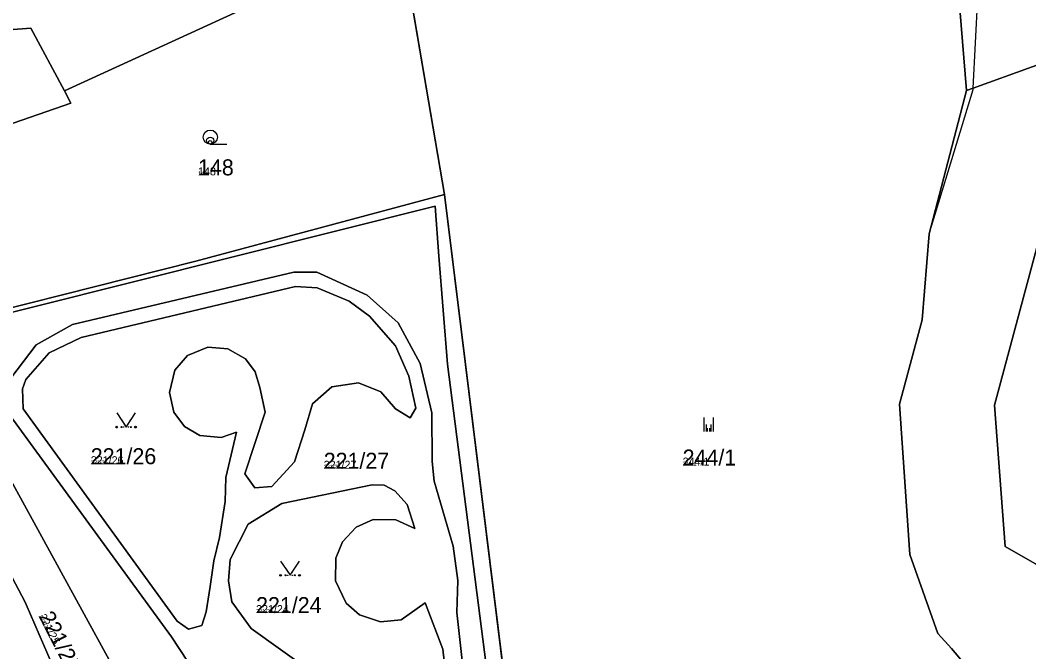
# Model space of a CAD drawing. Extents: x -759873 to -758487, y -975024 to -973516.
# Drawn here: x -759272.8 to -759165.8, y -974542 to -974475 of the extents above; entities that cross this region are included whole.
import ezdxf

# ---------------------------------------------------------------- set-up
doc = ezdxf.new("R2010")
doc.units = 0
for name, color, linetype in [('KAT_02_hranice parcel', 7, 'Continuous'), ('KAT_03_1000_čísla parcelní', 7, 'Continuous'), ('KAT_03_250_čísla parcelní', 7, 'Continuous'), ('KAT_03_500_čísla parcelní', 7, 'Continuous'), ('KAT_04_vnitřní kresba', 7, 'Continuous'), ('KAT_05_1000_značky kultur', 7, 'Continuous'), ('KAT_05_250_značky kultur', 7, 'Continuous'), ('KAT_05_500_značky kultur', 7, 'Continuous'), ('KAT_14_plocha_pozemek', 7, 'Continuous')]:
    doc.layers.add(name, color=color, linetype=linetype)

msp = doc.modelspace()

# ---------------------------------------------------------------- linework, layer by layer
at = {"layer": 'KAT_02_hranice parcel'}
for p, q in [((-759227.79, -974493.47), (-759232.25, -974467.32)), ((-759268.15, -974482.46), (-759249.19, -974473.79)), ((-759219.91, -974557.23), (-759227.79, -974493.47))]:
    msp.add_line(p, q, dxfattribs=at)
for points in [[(-759191.99, -974436.47), (-759175.27, -974446.88), (-759172.37, -974482.45)], [(-759293.31, -974472.92), (-759292.86, -974472.72), (-759290.03, -974471.45), (-759286.14, -974469.75), (-759281.32, -974467.51), (-759277.88, -974471.27), (-759274.04, -974476.01), (-759271.7, -974475.81), (-759268.15, -974482.46)], [(-759172.37, -974482.45), (-759171.66, -974482.19), (-759159.14, -974477.67)], [(-759275.54, -974505.92), (-759276.79, -974504.06), (-759278.82, -974487.7), (-759267.45, -974483.78), (-759268.15, -974482.46)], [(-759124.04, -974618.94), (-759128.67, -974614.12), (-759132.72, -974605.42), (-759137.89, -974601.46), (-759140.41, -974591.83), (-759141.66, -974587.58), (-759147.81, -974582.84), (-759161.09, -974585.41), (-759165.12, -974579.47), (-759166.21, -974570.14), (-759161.85, -974571.03), (-759164.75, -974552.56), (-759173.97, -974541.64), (-759175.43, -974540.05), (-759178.37, -974531.68), (-759179.47, -974515.71), (-759177.07, -974506.79), (-759176.34, -974497.63), (-759172.37, -974482.45)], [(-759149.95, -974565.4), (-759151.3, -974564.28), (-759155.66, -974538.03), (-759168.27, -974530.82), (-759169.41, -974515.83), (-759161.57, -974486.7)], [(-759275.54, -974505.92), (-759254.2, -974500.54), (-759227.79, -974493.47)], [(-759219.91, -974557.23), (-759223.23, -974544.52), (-759227.46, -974511.48), (-759228.38, -974500), (-759228.8, -974494.72), (-759282.45, -974508.14), (-759262.36, -974544.72), (-759253.18, -974586.18)], [(-759273.84, -974512.95), (-759271.16, -974509.41), (-759267.29, -974507.26), (-759243.79, -974501.7), (-759241.36, -974501.72), (-759236.02, -974504.15), (-759232.73, -974507.08), (-759230.36, -974511.4), (-759229.15, -974516.63), (-759229.1, -974521.82), (-759228.9, -974523.89), (-759226.87, -974530.81), (-759226.36, -974534.43), (-759226.47, -974537.82), (-759225.79, -974544.19), (-759225.71, -974548.4), (-759226.68, -974552.72), (-759228.4, -974556.94), (-759229.16, -974561.24), (-759228.07, -974563.77), (-759226.33, -974565.91), (-759215.26, -974578.73), (-759212.49, -974582.87), (-759209.02, -974593.36)], [(-759272.26, -974513.11), (-759272.59, -974514.08), (-759272.51, -974516.23), (-759256.19, -974538.76), (-759254.97, -974539.61), (-759253.54, -974539.23), (-759253.08, -974537.78), (-759252.69, -974535.06), (-759252.3, -974532.34), (-759251.69, -974529.88), (-759251.07, -974526.05), (-759251, -974523.49), (-759249.89, -974518.71), (-759251.5, -974519.25), (-759253.76, -974519.05), (-759255.41, -974518.08), (-759256.54, -974516.57), (-759257, -974514.49), (-759256.43, -974512.13), (-759255.09, -974510.57), (-759252.92, -974509.67), (-759250.79, -974509.85), (-759248.93, -974510.92), (-759247.9, -974512.28), (-759247.4, -974513.94), (-759246.82, -974516.59), (-759248.98, -974523.12), (-759247.94, -974524.6), (-759246.14, -974524.47), (-759243.73, -974521.83), (-759242.63, -974518.45), (-759241.8, -974515.68), (-759239.77, -974513.88), (-759236.91, -974513.45), (-759234.55, -974514.41), (-759232.99, -974516.23), (-759231.44, -974517.16), (-759230.83, -974516.16), (-759231.59, -974512.74), (-759232.98, -974509.54), (-759235.77, -974506.4), (-759237.92, -974504.78), (-759241.32, -974503.36), (-759243.61, -974503.25), (-759266.37, -974508.64), (-759269.77, -974510.26), (-759272.26, -974513.11)], [(-759258.04, -974584.15), (-759260.14, -974570.39), (-759263.44, -974559.14), (-759268.52, -974545.49), (-759272.2, -974537), (-759272.35, -974536.66), (-759278.72, -974524.68), (-759280.47, -974521.55), (-759287.48, -974507.08)], [(-759252.43, -974552.91), (-759254.18, -974544.35), (-759256.77, -974540.42), (-759273.95, -974516.88)], [(-759227.37, -974547), (-759227.98, -974541.74), (-759229.85, -974536.8), (-759232.4, -974538.61), (-759234.59, -974538.83), (-759236.81, -974538.09), (-759238.25, -974536.86), (-759239.38, -974534.47), (-759239.33, -974532.08), (-759238.61, -974530.35), (-759237.18, -974528.79), (-759235.36, -974527.97), (-759232.96, -974527.99), (-759230.96, -974528.93), (-759231.75, -974526.38), (-759233.07, -974524.92), (-759234.19, -974524.32), (-759235.47, -974524.3), (-759245.05, -974526.26), (-759248.65, -974528.45), (-759250.54, -974532.22), (-759250.74, -974534.47), (-759250.36, -974536.71), (-759248.31, -974539.55), (-759241.84, -974544.16)]]:
    msp.add_lwpolyline(points, dxfattribs=at)
at = {"layer": 'KAT_04_vnitřní kresba'}
for p, q in [((-759171.66, -974482.19), (-759170.77, -974464.99)), ((-759176.34, -974497.63), (-759171.67, -974482.33)), ((-759171.67, -974482.33), (-759171.66, -974482.19))]:
    msp.add_line(p, q, dxfattribs=at)
at = {"layer": 'KAT_05_1000_značky kultur'}
for p, q in [((-759252.66, -974488.13), (-759250.91, -974488.13)), ((-759200.24, -974518.64), (-759200.24, -974517.14)), ((-759199.24, -974518.64), (-759199.24, -974517.14))]:
    msp.add_line(p, q, dxfattribs=at)
for points in [[(-759262.6, -974516.65), (-759261.6, -974518.15), (-759260.6, -974516.65)], [(-759245.19, -974532.39), (-759244.19, -974533.89), (-759243.19, -974532.39)]]:
    msp.add_lwpolyline(points, dxfattribs=at)
for centre, radius in [((-759252.66, -974487.38), 0.75), ((-759262.6, -974518.15), 0.1), ((-759260.6, -974518.15), 0.1), ((-759245.19, -974533.89), 0.1), ((-759243.19, -974533.89), 0.1)]:
    msp.add_circle(centre, radius, dxfattribs=at)
at = {"layer": 'KAT_05_250_značky kultur'}
for p, q in [((-759252.67, -974488.13), (-759252.23, -974488.13)), ((-759199.86, -974518.64), (-759199.86, -974518.27)), ((-759199.61, -974518.64), (-759199.61, -974518.27))]:
    msp.add_line(p, q, dxfattribs=at)
for points in [[(-759261.85, -974517.77), (-759261.6, -974518.15), (-759261.35, -974517.77)], [(-759244.44, -974533.51), (-759244.19, -974533.89), (-759243.94, -974533.51)]]:
    msp.add_lwpolyline(points, dxfattribs=at)
for centre, radius in [((-759252.67, -974487.94), 0.187), ((-759261.85, -974518.15), 0.025), ((-759261.35, -974518.15), 0.025), ((-759244.44, -974533.89), 0.025), ((-759243.94, -974533.89), 0.025)]:
    msp.add_circle(centre, radius, dxfattribs=at)
at = {"layer": 'KAT_05_500_značky kultur'}
for p, q in [((-759252.67, -974488.13), (-759251.79, -974488.13)), ((-759199.99, -974518.64), (-759199.99, -974517.89)), ((-759199.48, -974518.64), (-759199.48, -974517.89))]:
    msp.add_line(p, q, dxfattribs=at)
for points in [[(-759262.1, -974517.4), (-759261.6, -974518.15), (-759261.1, -974517.4)], [(-759244.69, -974533.14), (-759244.19, -974533.89), (-759243.69, -974533.14)]]:
    msp.add_lwpolyline(points, dxfattribs=at)
for centre, radius in [((-759252.67, -974487.75), 0.375), ((-759262.1, -974518.15), 0.05), ((-759261.1, -974518.15), 0.05), ((-759244.69, -974533.89), 0.05), ((-759243.69, -974533.89), 0.05)]:
    msp.add_circle(centre, radius, dxfattribs=at)
at = {"layer": 'KAT_14_plocha_pozemek'}
for points in [[(-759175.27, -974446.88), (-759172.37, -974482.45), (-759171.66, -974482.19), (-759159.14, -974477.67), (-759164.42, -974455.5), (-759165.63, -974450.4), (-759168.64, -974433.81), (-759181.64, -974397.69), (-759189.03, -974384.96), (-759194.73, -974407.56), (-759206.79, -974400.97), (-759217.05, -974393.25), (-759219.59, -974401.14), (-759220.81, -974404.94), (-759225.77, -974404.63), (-759227.77, -974404.51), (-759229.03, -974406.06), (-759225.39, -974407.7), (-759207.13, -974415.97), (-759198.3, -974417.97), (-759197.39, -974426.02), (-759191.99, -974436.47)], [(-759249.19, -974473.79), (-759253.23, -974463.77), (-759260.24, -974446.55), (-759283.67, -974455.79), (-759289.33, -974460.28), (-759293.75, -974468.73), (-759293.31, -974472.92), (-759292.86, -974472.72), (-759290.03, -974471.45), (-759286.14, -974469.75), (-759281.32, -974467.51), (-759277.88, -974471.27), (-759274.04, -974476.01), (-759271.7, -974475.81), (-759268.15, -974482.46)], [(-759287.48, -974507.08), (-759275.54, -974505.92), (-759276.79, -974504.06), (-759278.82, -974487.7), (-759267.45, -974483.78), (-759268.15, -974482.46), (-759271.7, -974475.81), (-759274.04, -974476.01), (-759277.88, -974471.27), (-759281.32, -974467.51), (-759286.14, -974469.75), (-759290.03, -974471.45), (-759292.86, -974472.72), (-759293.31, -974472.92), (-759296.17, -974474.22), (-759296.19, -974481.83), (-759295.36, -974491.46), (-759292.96, -974492.33), (-759285.34, -974489.62), (-759281.99, -974499.18), (-759289.52, -974501.85)], [(-759227.79, -974493.47), (-759232.25, -974467.32), (-759249.19, -974473.79), (-759268.15, -974482.46), (-759267.45, -974483.78), (-759278.82, -974487.7), (-759276.79, -974504.06), (-759275.54, -974505.92), (-759254.2, -974500.54)], [(-759131.21, -974524.03), (-759125.93, -974515.33), (-759144.9, -974503.66), (-759150.51, -974493.42), (-759161.57, -974486.7), (-759169.41, -974515.83), (-759168.27, -974530.82), (-759155.66, -974538.03), (-759151.3, -974564.28), (-759149.95, -974565.4), (-759139.11, -974538.34)], [(-759219.91, -974557.23), (-759227.79, -974493.47), (-759254.2, -974500.54), (-759275.54, -974505.92), (-759287.48, -974507.08), (-759280.47, -974521.55), (-759278.72, -974524.68), (-759272.35, -974536.66), (-759272.2, -974537), (-759268.52, -974545.49), (-759263.44, -974559.14), (-759260.14, -974570.39), (-759258.04, -974584.15), (-759256.76, -974585.37), (-759255.85, -974585.97), (-759255.42, -974586.26), (-759253.18, -974586.18), (-759262.36, -974544.72), (-759282.45, -974508.14), (-759228.8, -974494.72), (-759228.38, -974500), (-759227.46, -974511.48), (-759223.23, -974544.52)], [(-759272.26, -974513.11), (-759272.59, -974514.08), (-759272.51, -974516.23), (-759256.19, -974538.76), (-759254.97, -974539.61), (-759253.54, -974539.23), (-759253.08, -974537.78), (-759252.69, -974535.06), (-759252.3, -974532.34), (-759251.69, -974529.88), (-759251.07, -974526.05), (-759251, -974523.49), (-759249.89, -974518.71), (-759251.5, -974519.25), (-759253.76, -974519.05), (-759255.41, -974518.08), (-759256.54, -974516.57), (-759257, -974514.49), (-759256.43, -974512.13), (-759255.09, -974510.57), (-759252.92, -974509.67), (-759250.79, -974509.85), (-759248.93, -974510.92), (-759247.9, -974512.28), (-759247.4, -974513.94), (-759246.82, -974516.59), (-759248.98, -974523.12), (-759247.94, -974524.6), (-759246.14, -974524.47), (-759243.73, -974521.83), (-759242.63, -974518.45), (-759241.8, -974515.68), (-759239.77, -974513.88), (-759236.91, -974513.45), (-759234.55, -974514.41), (-759232.99, -974516.23), (-759231.44, -974517.16), (-759230.83, -974516.16), (-759231.59, -974512.74), (-759232.98, -974509.54), (-759235.77, -974506.4), (-759237.92, -974504.78), (-759241.32, -974503.36), (-759243.61, -974503.25), (-759266.37, -974508.64), (-759269.77, -974510.26)], [(-759272.26, -974513.11), (-759269.77, -974510.26), (-759266.37, -974508.64), (-759243.61, -974503.25), (-759241.32, -974503.36), (-759237.92, -974504.78), (-759235.77, -974506.4), (-759232.98, -974509.54), (-759231.59, -974512.74), (-759230.83, -974516.16), (-759231.44, -974517.16), (-759232.99, -974516.23), (-759234.55, -974514.41), (-759236.91, -974513.45), (-759239.77, -974513.88), (-759241.8, -974515.68), (-759242.63, -974518.45), (-759243.73, -974521.83), (-759246.14, -974524.47), (-759247.94, -974524.6), (-759248.98, -974523.12), (-759246.82, -974516.59), (-759247.4, -974513.94), (-759247.9, -974512.28), (-759248.93, -974510.92), (-759250.79, -974509.85), (-759252.92, -974509.67), (-759255.09, -974510.57), (-759256.43, -974512.13), (-759257, -974514.49), (-759256.54, -974516.57), (-759255.41, -974518.08), (-759253.76, -974519.05), (-759251.5, -974519.25), (-759249.89, -974518.71), (-759251, -974523.49), (-759251.07, -974526.05), (-759251.69, -974529.88), (-759252.3, -974532.34), (-759252.69, -974535.06), (-759253.08, -974537.78), (-759253.54, -974539.23), (-759254.97, -974539.61), (-759256.19, -974538.76), (-759272.51, -974516.23), (-759272.59, -974514.08)]]:
    msp.add_lwpolyline(points, close=True, dxfattribs=at)
for points in [[(-759164.75, -974552.56), (-759173.97, -974541.64), (-759175.43, -974540.05), (-759178.37, -974531.68), (-759179.47, -974515.71), (-759177.07, -974506.79), (-759176.34, -974497.63), (-759172.37, -974482.45), (-759175.27, -974446.88)], [(-759232.25, -974467.32), (-759227.79, -974493.47), (-759219.91, -974557.23), (-759217.96, -974564.68), (-759183.74, -974565.93), (-759174.05, -974595), (-759148.58, -974619.46)], [(-759159.14, -974477.67), (-759171.66, -974482.19), (-759172.37, -974482.45), (-759176.34, -974497.63), (-759177.07, -974506.79), (-759179.47, -974515.71), (-759178.37, -974531.68), (-759175.43, -974540.05), (-759173.97, -974541.64), (-759164.75, -974552.56)], [(-759155.66, -974538.03), (-759168.27, -974530.82), (-759169.41, -974515.83), (-759161.57, -974486.7)], [(-759223.23, -974544.52), (-759227.46, -974511.48), (-759228.38, -974500), (-759228.8, -974494.72), (-759282.45, -974508.14), (-759262.36, -974544.72)], [(-759225.79, -974544.19), (-759226.47, -974537.82), (-759226.36, -974534.43), (-759226.87, -974530.81), (-759228.9, -974523.89), (-759229.1, -974521.82), (-759229.15, -974516.63), (-759230.36, -974511.4), (-759232.73, -974507.08), (-759236.02, -974504.15), (-759241.36, -974501.72), (-759243.79, -974501.7), (-759267.29, -974507.26), (-759271.16, -974509.41), (-759273.84, -974512.95)], [(-759273.84, -974512.95), (-759271.16, -974509.41), (-759267.29, -974507.26), (-759243.79, -974501.7), (-759241.36, -974501.72), (-759236.02, -974504.15), (-759232.73, -974507.08), (-759230.36, -974511.4), (-759229.15, -974516.63), (-759229.1, -974521.82), (-759228.9, -974523.89), (-759226.87, -974530.81), (-759226.36, -974534.43), (-759226.47, -974537.82), (-759225.79, -974544.19)], [(-759273.95, -974516.88), (-759256.77, -974540.42), (-759254.18, -974544.35)], [(-759254.18, -974544.35), (-759256.77, -974540.42), (-759273.95, -974516.88)], [(-759227.37, -974547), (-759227.98, -974541.74), (-759229.85, -974536.8), (-759232.4, -974538.61), (-759234.59, -974538.83), (-759236.81, -974538.09), (-759238.25, -974536.86), (-759239.38, -974534.47), (-759239.33, -974532.08), (-759238.61, -974530.35), (-759237.18, -974528.79), (-759235.36, -974527.97), (-759232.96, -974527.99), (-759230.96, -974528.93), (-759231.75, -974526.38), (-759233.07, -974524.92), (-759234.19, -974524.32), (-759235.47, -974524.3), (-759245.05, -974526.26), (-759248.65, -974528.45), (-759250.54, -974532.22), (-759250.74, -974534.47), (-759250.36, -974536.71), (-759248.31, -974539.55), (-759241.84, -974544.16)], [(-759241.84, -974544.16), (-759248.31, -974539.55), (-759250.36, -974536.71), (-759250.74, -974534.47), (-759250.54, -974532.22), (-759248.65, -974528.45), (-759245.05, -974526.26), (-759235.47, -974524.3), (-759234.19, -974524.32), (-759233.07, -974524.92), (-759231.75, -974526.38), (-759230.96, -974528.93), (-759232.96, -974527.99), (-759235.36, -974527.97), (-759237.18, -974528.79), (-759238.61, -974530.35), (-759239.33, -974532.08), (-759239.38, -974534.47), (-759238.25, -974536.86), (-759236.81, -974538.09), (-759234.59, -974538.83), (-759232.4, -974538.61), (-759229.85, -974536.8), (-759227.98, -974541.74), (-759227.37, -974547)], [(-759268.52, -974545.49), (-759272.2, -974537), (-759272.35, -974536.66), (-759278.72, -974524.68)]]:
    msp.add_lwpolyline(points, dxfattribs=at)

# ---------------------------------------------------------------- texts
at = {"layer": 'KAT_03_1000_čísla parcelní'}
for s, p in [('148', (-759253.96, -974491.44)), ('221/26', (-759265.35, -974522.1)), ('221/27', (-759240.62, -974522.58)), ('244/1', (-759202.51, -974522.24)), ('221/24', (-759247.8, -974537.9))]:
    msp.add_text(s, height=1.7, dxfattribs=at).set_placement(p)
msp.add_text('221/25', height=1.7, rotation=297, dxfattribs=at).set_placement((-759270.9, -974538.23))
at = {"layer": 'KAT_03_250_čísla parcelní'}
for s, p in [('148', (-759253.96, -974491.44)), ('221/26', (-759265.35, -974522.1)), ('221/27', (-759240.62, -974522.58)), ('244/1', (-759202.51, -974522.24)), ('221/24', (-759247.8, -974537.9))]:
    msp.add_text(s, height=0.425, dxfattribs=at).set_placement(p)
msp.add_text('221/25', height=0.425, rotation=297, dxfattribs=at).set_placement((-759270.9, -974538.23))
at = {"layer": 'KAT_03_500_čísla parcelní'}
for s, p in [('148', (-759253.96, -974491.44)), ('221/26', (-759265.35, -974522.1)), ('221/27', (-759240.62, -974522.58)), ('244/1', (-759202.51, -974522.24)), ('221/24', (-759247.8, -974537.9))]:
    msp.add_text(s, height=0.85, dxfattribs=at).set_placement(p)
msp.add_text('221/25', height=0.85, rotation=297, dxfattribs=at).set_placement((-759270.9, -974538.23))

doc.saveas('drawing.dxf')
